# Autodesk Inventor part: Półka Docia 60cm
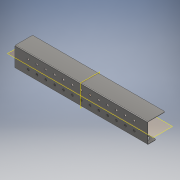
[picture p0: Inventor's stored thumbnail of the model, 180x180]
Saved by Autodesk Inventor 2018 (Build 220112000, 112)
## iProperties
Created: 2020-02
Part Number: Półka Docia 60cm
Material: Ogólny
Document SubType Name: Modeling
Designer: Marcel
Density: 1 g/cm^3
Appearance: Domyślna
Author: Marcel
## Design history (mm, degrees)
derived "Półka Docia 60 cm.iam"
node "Bryła1"
node "Półka prysznicowa - 60 cm.ipt:1"
node "Płaszczyzna konstrukcyjna1"
node "Płaszczyzna konstrukcyjna2"
node "Kapselek.ipt:1"
node "Kapselek.ipt:2"
